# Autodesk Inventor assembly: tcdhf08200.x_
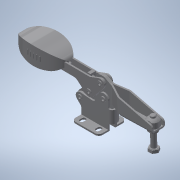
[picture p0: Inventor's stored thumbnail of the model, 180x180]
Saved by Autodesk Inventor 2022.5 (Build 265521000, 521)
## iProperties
Created: 2020-04
Part Number: tcdhf08200.x_
Material: 一般
Document SubType Name: Assembly
Designer: ImaoCorp
Sending System: SOLIDWORKS 2018-2018316
MC: AMD64
MC_MODEL: Intel64 Family 6 Model 60 Stepping 3, GenuineIntel
OS: Windows_NT
FRU: Parasolid Version 30.0, build 310,  6- 8-2018
FORMAT: text
GUISE: transmit
KEY: tcdhf08200
FILE: tcdhf08200.x_t
DATE: Wed Apr 15 11:48:37 2020
Author: ImaoCorp
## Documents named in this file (8)
- X:\14_SW2022-Inv2022\00_全2023-1023新製品(TCC)まで\t\tcdhf08200\TCDHF08200.iam
- X:\14_SW2022-Inv2022\00_全2023-1023新製品(TCC)まで\t\tcdhf08200\tcdhf08200_01.ipt
- X:\14_SW2022-Inv2022\00_全2023-1023新製品(TCC)まで\t\tcdhf08200\tcdhf08200_02.ipt
- X:\14_SW2022-Inv2022\00_全2023-1023新製品(TCC)まで\t\tcdhf08200\tcdhf08200_03.ipt
- X:\14_SW2022-Inv2022\00_全2023-1023新製品(TCC)まで\t\tcdhf08200\tcdhf08200_04.ipt
- X:\14_SW2022-Inv2022\00_全2023-1023新製品(TCC)まで\t\tcdhf08200\tcdhf08200_05.ipt
- X:\14_SW2022-Inv2022\00_全2023-1023新製品(TCC)まで\t\tcdhf08200\tcdhf08200_06.ipt
- X:\14_SW2022-Inv2022\00_全2023-1023新製品(TCC)まで\t\tcdhf08200\tcdhf08200_07.ipt
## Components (7 placed, 7 different names)
1. tcdhf08200_01
2. tcdhf08200_02
3. tcdhf08200_03
4. tcdhf08200_04
5. tcdhf08200_05
6. tcdhf08200_06
7. tcdhf08200_07
